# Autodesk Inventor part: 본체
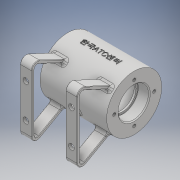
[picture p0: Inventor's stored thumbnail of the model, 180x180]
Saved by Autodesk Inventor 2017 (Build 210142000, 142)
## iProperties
Part Number: 본체
Material: 일반
Document SubType Name: Modeling
Designer: Administrator
Density: 1 g/cm^3
Appearance: 기본값
Mass: 114.728 g
Surface Area: 353.837 cm^2
Volume: 114.728 cm^3
Author: Administrator
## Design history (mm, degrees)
sketch "스케치1"
  geometry: L1 (0, 0)-(70, 0); L2 (0, 29)-(70, 29); L3 (70, 29)-(70, 16); L4 (70, 16)-(58, 16); L5 (58, 16)-(58, 14); L6 (58, 14)-(56, 14); L7 (56, 14)-(56, 21); L8 (56, 21)-(14, 21); L9 (14, 21)-(14, 14); L10 (14, 14)-(12, 14); L11 (12, 14)-(12, 16); L12 (12, 16)-(0, 16); L13 (0, 16)-(0, 29)
  constraints: 26 end point, 10 perpendicular, 2 horizontal, 2 point on line, 2 vertical alignment
  dimensions: "d0" = 70 distance of L1.start L1.end; "d1" = 58 diameter of L2 L1; "d2" = 42 diameter of L8 L1; "d3" = 28 diameter of L10 L1; "d4" = 32 diameter of L4 L1; "d5" = 32 diameter of L12 L1; "d6" = 12 distance of L11.end L12.end; "d7" = 42 distance of L7.end L8.end; "d8" = 12 distance of L3.end L4.end; "d9" = 2 distance of L5.end L6.end
revolve "회전1" sketch "스케치1" stored, may be unused: angle "d10" = 90 deg
node "작업 평면1"
sketch "스케치2"
  geometry: L1 (0, 29)-(0, -29) reference; C1 r 5 at (-35, 0); 1 further point
  constraints: 1 centre point, 1 horizontal alignment
  dimensions: "d12" = 10 diameter of C1; "d13" = 35 distance from line of C1.centre L1
extrude "돌출1" join sketch "스케치2" stored distance "d14" = 10; taper "d15" = 0 deg
node "작업 평면2"
sketch "스케치4"
  geometry: L1 (0, 0)-(34.074, 0); L2 (0, 0)-(30.07, -10.945); L3 (0, 0)-(32, 0)
  constraints: 6 end point, 2 horizontal, 1 equal length
  dimensions: "d18" = 32 distance of L1.start L2.end; "d19" = 20 deg angle of L2 L3; "d43" = 34.07448 distance of L1.start L1.end
node "작업 평면3"
sketch "스케치5"
  geometry: C1 r 6 at (0, 0); 4 further points
  constraints: 1 centre point, 1 coincident
  dimensions: "d20" = 12 diameter of C1
extrude "돌출2" join sketch "스케치5" stored distance "d21" = 10; taper "d22" = 0 deg
node "작업 평면5"
sketch "스케치8"
  geometry: L1 (20.15, -20.856)-(46.064, -35.399); L2 (55, -30.167)-(55, 30.167); L3 (46.464, 35.605)-(18.32, 22.481); L4 (20.72, 20.29)-(47.732, 32.886); L5 (52, 30.167)-(52, -30.167); L6 (47.532, -32.783)-(22.253, -18.596); A1 r 29 centre (0, 0) between (20.15, -20.856) and (18.32, 22.481) reference; A2 r 29 centre (0, 0) between (20.15, -20.856) and (18.32, 22.481) reference; A3 r 6 centre (49, 30.167) between (55, 30.167) and (46.464, 35.605); A4 r 6 centre (49, -30.167) between (46.064, -35.399) and (55, -30.167); A5 r 3 centre (49, 30.167) between (52, 30.167) and (47.732, 32.886); A6 r 3 centre (49, -30.167) between (47.532, -32.783) and (52, -30.167); 4 further points
  constraints: 14 point on circle, 12 end point, 4 centre point, 4 point on line, 4 tangent, 1 equal radius, 1 horizontal alignment, 1 midpoint, 1 vertical, 2 other
  dimensions: "d32" = 80 distance of point (55, -40.415) point (55, 39.585); "d33" = 55 distance from line of L2 A1.centre; "d35" = 65 deg angle of L2 L3; "d36" = 6 radius of A3; "d37" = 3 distance between parallel lines of L3 L4; "d38" = 60.6979 deg angle of L1 L2; "d39" = 3 distance between parallel lines of L6 L1; "d40" = 3 distance between parallel lines of L2 L5
extrude "돌출3" join sketch "스케치8" distance "d41" = 12; taper "d42" = 0 deg
sketch "스케치9"
  geometry: L1 (0, 60.334)-(0, 0) reference; C1 r 3 at (6, 48.167); C2 r 3 at (6, 12.167); 1 further point
  constraints: 2 centre point, 1 vertical alignment
  dimensions: "d44" = 6 diameter of C1; "d45" = 6 diameter of C2; "d46" = 36 distance of C2.centre C1.centre; "d47" = 6 distance from line of C1.centre L1; "d48" = 18 vertical distance of point (-5, 30.167) C1.centre
extrude "돌출4" cut sketch "스케치9" distance "d49" = 12; taper "d50" = 0 deg
node "작업 평면6"
sketch "스케치10"
  geometry: 3 further points
  constraints: 2 horizontal alignment, 1 other
hole "구멍1" sketch "스케치10" at (21, 0) diameter "d52" = 3.242; stored, may be unused: countersink angle "d56" = 90 deg, drill point angle "d58" = 118 deg; dims "d53" = 8, "d54" = 4, "d55" = 2, "d57" = 10
hole "구멍2" diameter "d64" = 3; stored, may be unused: countersink angle "d68" = 90 deg, drill point angle "d70" = 118 deg; dims "d62" = 10, "d63" = 10, "d65" = 6, "d66" = 4, "d67" = 2, "d69" = 30
hole "구멍3" diameter "d73" = 5.188; stored, may be unused: countersink angle "d77" = 90 deg, drill point angle "d79" = 118 deg; dims "d71" = 10, "d72" = 10, "d74" = 6, "d75" = 4, "d76" = 2, "d78" = 8
fillet "모깎기1" dims "d80" = 3
fillet "모깎기2" dims "d81" = 0.3
chamfer "모따기1" distance "d82" = 1; stored, may be unused: second distance "d83" = 2, angle "d84" = 45 deg
fillet "모깎기3" dims "d85" = 1
fillet "모깎기4" dims "d89" = 0.5
fillet "모깎기5" dims "d90" = 3
hole "구멍4" diameter "d93" = 5.188; stored, may be unused: countersink angle "d97" = 90 deg, drill point angle "d99" = 118 deg; dims "d91" = 10, "d92" = 10, "d94" = 12, "d95" = 4, "d96" = 2, "d98" = 16
node "작업 평면7"
sketch "스케치11"
  geometry: L1 (0, -29)-(0, 29) reference; L2 (0, 29)-(70, 29) reference; 2 further points
  constraints: 1 other
  dimensions: "d101" = 35 distance from line of point (35, 0) L1; "d102" = 29 distance from line of point (35, 0) L2
feature "엠보싱1" sketch "스케치11" dims "d0" = 70, "d1" = 58, "d2" = 42, "d3" = 28, "d4" = 32, "d5" = 32, "d6" = 12, "d7" = 42, "d8" = 12, "d9" = 2, "d103" = 0.5, "d104" = 0
node "솔리드1"
mirror "미러1"
pattern_circular "원형 패턴1" dims angle "d60" = 360 deg
mirror "미러2"
other parameters: "d11" = 32, "d16" = 35, "d31" = 5, "d100" = 90.25
